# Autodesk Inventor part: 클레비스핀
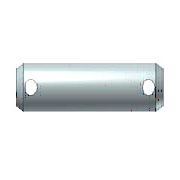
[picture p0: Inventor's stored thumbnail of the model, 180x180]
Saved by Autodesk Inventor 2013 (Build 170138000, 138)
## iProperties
IsCustomPart: 1
Created: 2012-02
Part Number: 클레비스핀
Material: 강철
Description: 머리가 없는 클레비스 핀 B
Document SubType Name: Modeling
Standard: ISO 2340
Designer: mduedu
Standard Revision: Second edition 1986-11-01
Standards Organization: ISO
Language: ko-KR
Size Designation: B - 8 x 45
Categories: <MemberInstance><Categories><Category DisplayName="조임쇠" InternalName="e4da775c-781d-43d5-af7c-5136215cf5a6" Mnemonic="FSTN"><Category DisplayName="핀" InternalNa
Density: 7.85 g/cm^3
Author: mduedu
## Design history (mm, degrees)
sketch "스케치1"
  geometry: L1 (-4.5, 0)-(-4.5, 4); L2 (-4.5, 4)-(40.5, 4); L3 (40.5, 4)-(40.5, 0); L4 (-4.5, 0)-(40.5, 0); L5 (0, -1.46)-(0, 3.16) reference; L6 (-6.4, 0)-(18.8, 0) reference; C1 r 1 at (-1, 0); C2 r 1 at (37, 0)
  constraints: 8 end point, 2 centre point, 2 perpendicular, 2 point on line, 1 collinear, 1 parallel, 1 tangent, 1 vertical
  dimensions: "d0" = 8 diameter of L2 L4 (= NND); "d1" = 45 distance of L1.end L2.end (= NLG); "d2" = 3.5 distance from line of L1 C1.centre (= DIST1); "d3" = 3.5 distance from line of L3 C2.centre (= DIST2); "d4" = 2 diameter of C1 (= BOR1); "d5" = 2 diameter of C2 (= BOR2)
revolve "본체" stored, may be unused: angle "d7" = 90 deg
extrude "구멍1" cut sketch "스케치1" taper "d6" = 0 deg; stored distance "d8" = 10
extrude "구멍2" cut sketch "스케치1" taper "d13" = 0 deg; stored distance "d14" = 10
workaxis "Work Axis1"
workaxis "Work Axis2"
workplane "Work Plane1"
node "작업 평면5"
body "Solid1"
chamfer "모따기2" distance "d9" = 2 (= PHH2); stored, may be unused: angle "d10" = 30 deg (= FAWI2), second distance "d40" = 2 (= PHH2)
chamfer "모따기1" distance "d11" = 2 (= PHH1); stored, may be unused: angle "d12" = 30 deg (= FAWI1), second distance "d41" = 2 (= PHH1)
other parameters: "NLG" = 45 [user parameter; used in 1 equation term], "NND" = 8 [user parameter; used in 1 equation term], "PHH1" = 2 [user parameter; used in 3 equation terms], "PHH2" = 2 (= PHH1) [user parameter; used in 2 equation terms], "FAWI1" = 30 deg [user parameter; used in 1 equation term], "FAWI2" = 30 deg [user parameter; used in 1 equation term], "DIST1" = 3.5 [user parameter; used in 4 equation terms], "DIST2" = 3.5 (= DIST1) [user parameter; used in 1 equation term], "BOR1" = 2 [user parameter; used in 4 equation terms], "BOR2" = 2 (= BOR1) [user parameter; used in 1 equation term], "d15" = 0, "d42" = 0, "d43" = 0, "d44" = -4.5 (= -0.5 x BOR1 - DIST1), "d45" = -4.5 (= -0.5 x BOR1 - DIST1), "d47" = 0, "d48" = 0, "d49" = 0, "d50" = 0, "d51" = 0, "d52" = 0
